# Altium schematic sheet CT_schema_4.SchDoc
size 293 x 258 mm
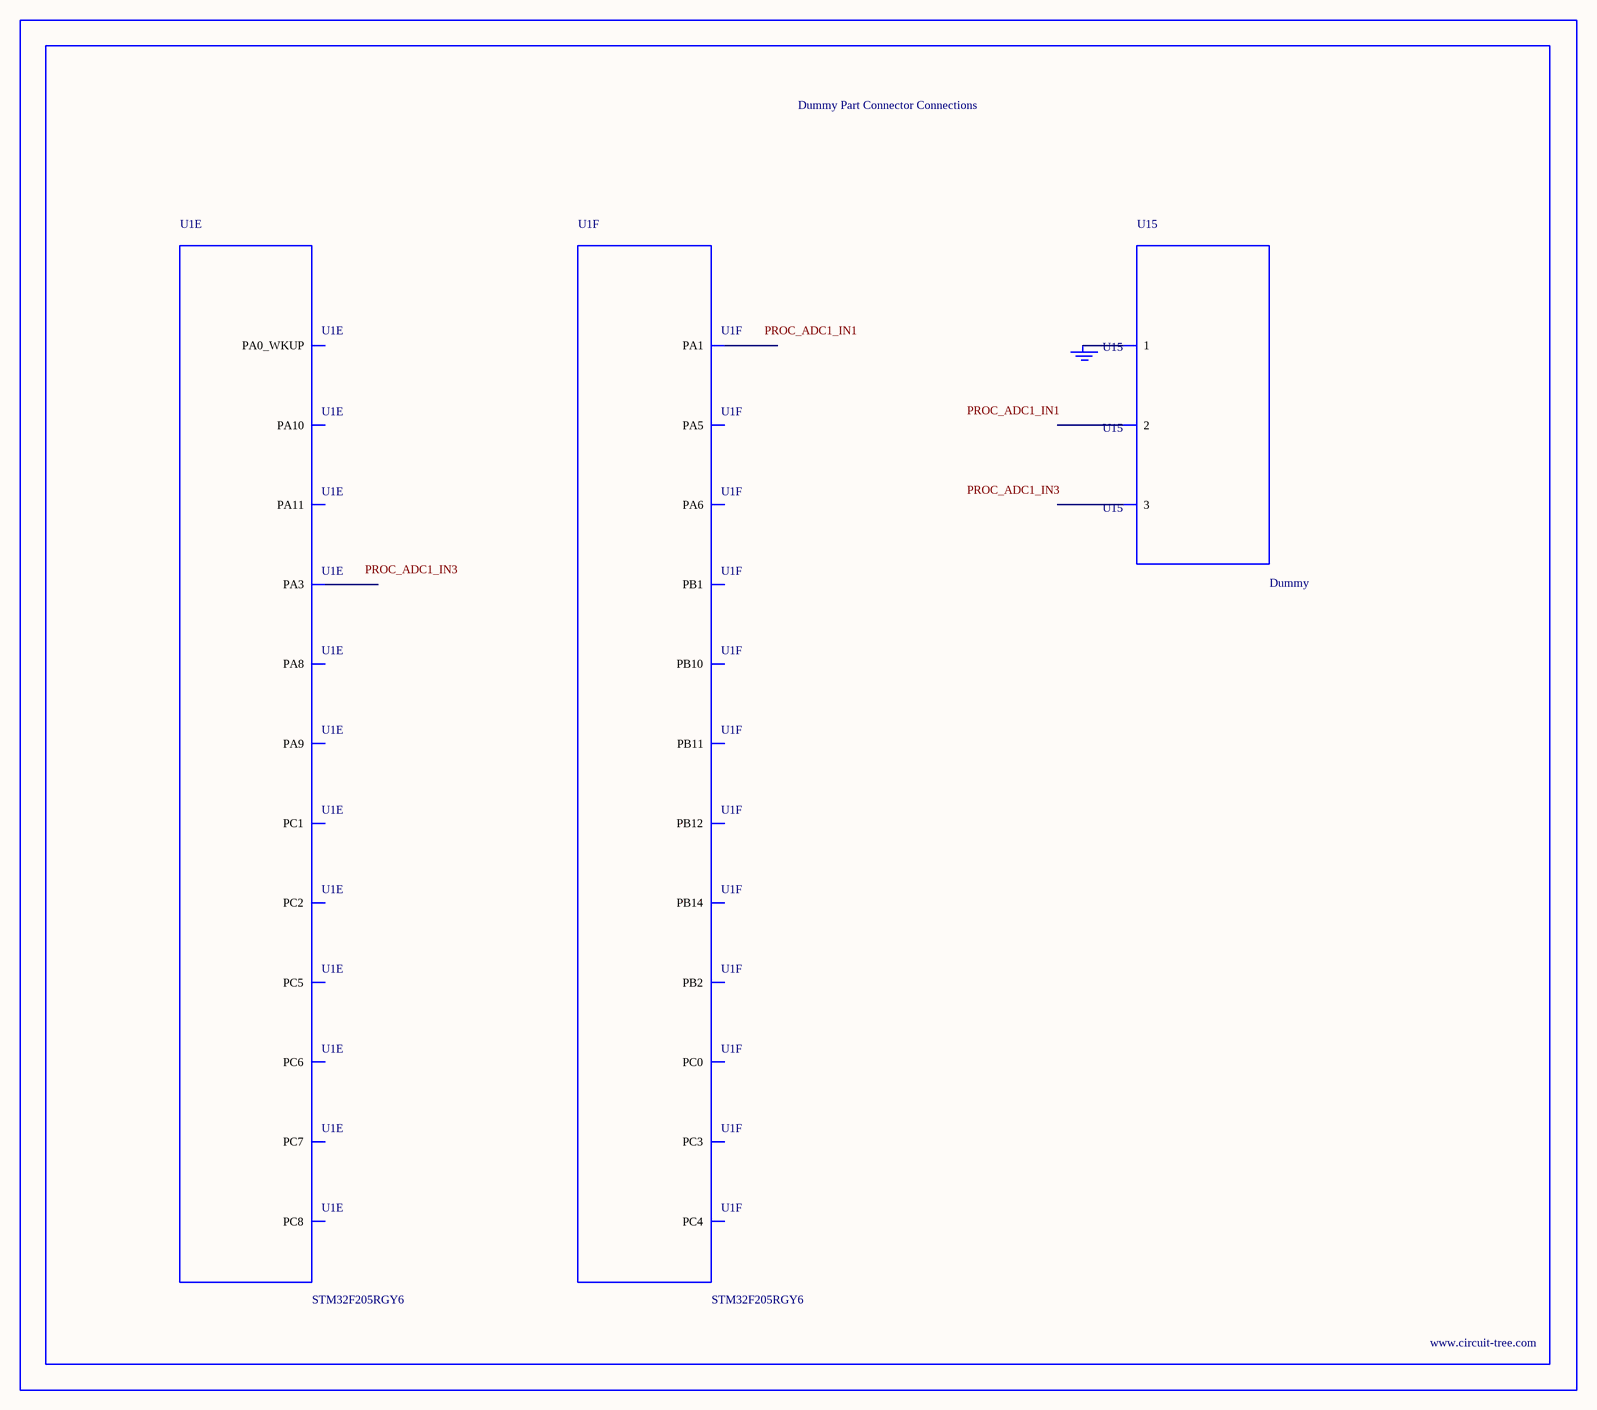
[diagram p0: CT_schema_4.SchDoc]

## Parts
BORDER3  (no value)
GND_INSTANCE_3_0  (no value)
U1  STM32F205RGY6  [WLCSP66]  (parts E,F of 6)
U15  Dummy  [DUMMY_PACKAGE_157]

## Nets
NetGND_INSTANCE_3_0_0: GND_INSTANCE_3_0.0(GND) U15.1

Not connected (* = marked no-connect by the designer): U1 D2(PA11) D3(PA10) D7(PC2) E2(PA8) E3(PA9) E7(PA0_WKUP) F2(PC7) F3(PC8) F8(PC1) G2(PC6) G3(PC5) G7(PA3) G8(PC3) G9(PC0) H1(PB14) H3(PB10) H4(PC4) H5(PA6) H6(PA5) H8(PA1) J1(PB12) J2(PB11) J4(PB2) J5(PB1); U15 2 3

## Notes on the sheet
- Labels drawn without touching a wire or pin: PROC_ADC1_IN1, PROC_ADC1_IN3

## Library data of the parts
BORDER3 = BORDER_PAGE3
GND_INSTANCE_3_0 = GND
